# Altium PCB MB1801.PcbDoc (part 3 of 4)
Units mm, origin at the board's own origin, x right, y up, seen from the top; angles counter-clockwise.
Board outline 70.1 x 57.1 mm, 4 copper layers (Top Layer, Signal Layer 1, Signal Layer 2, Bottom Layer), stack 1.614 mm thick; 219 components, 166 nets, 1002 pads, 473 vias.
Unrouted connection lines stored in the file: 2.
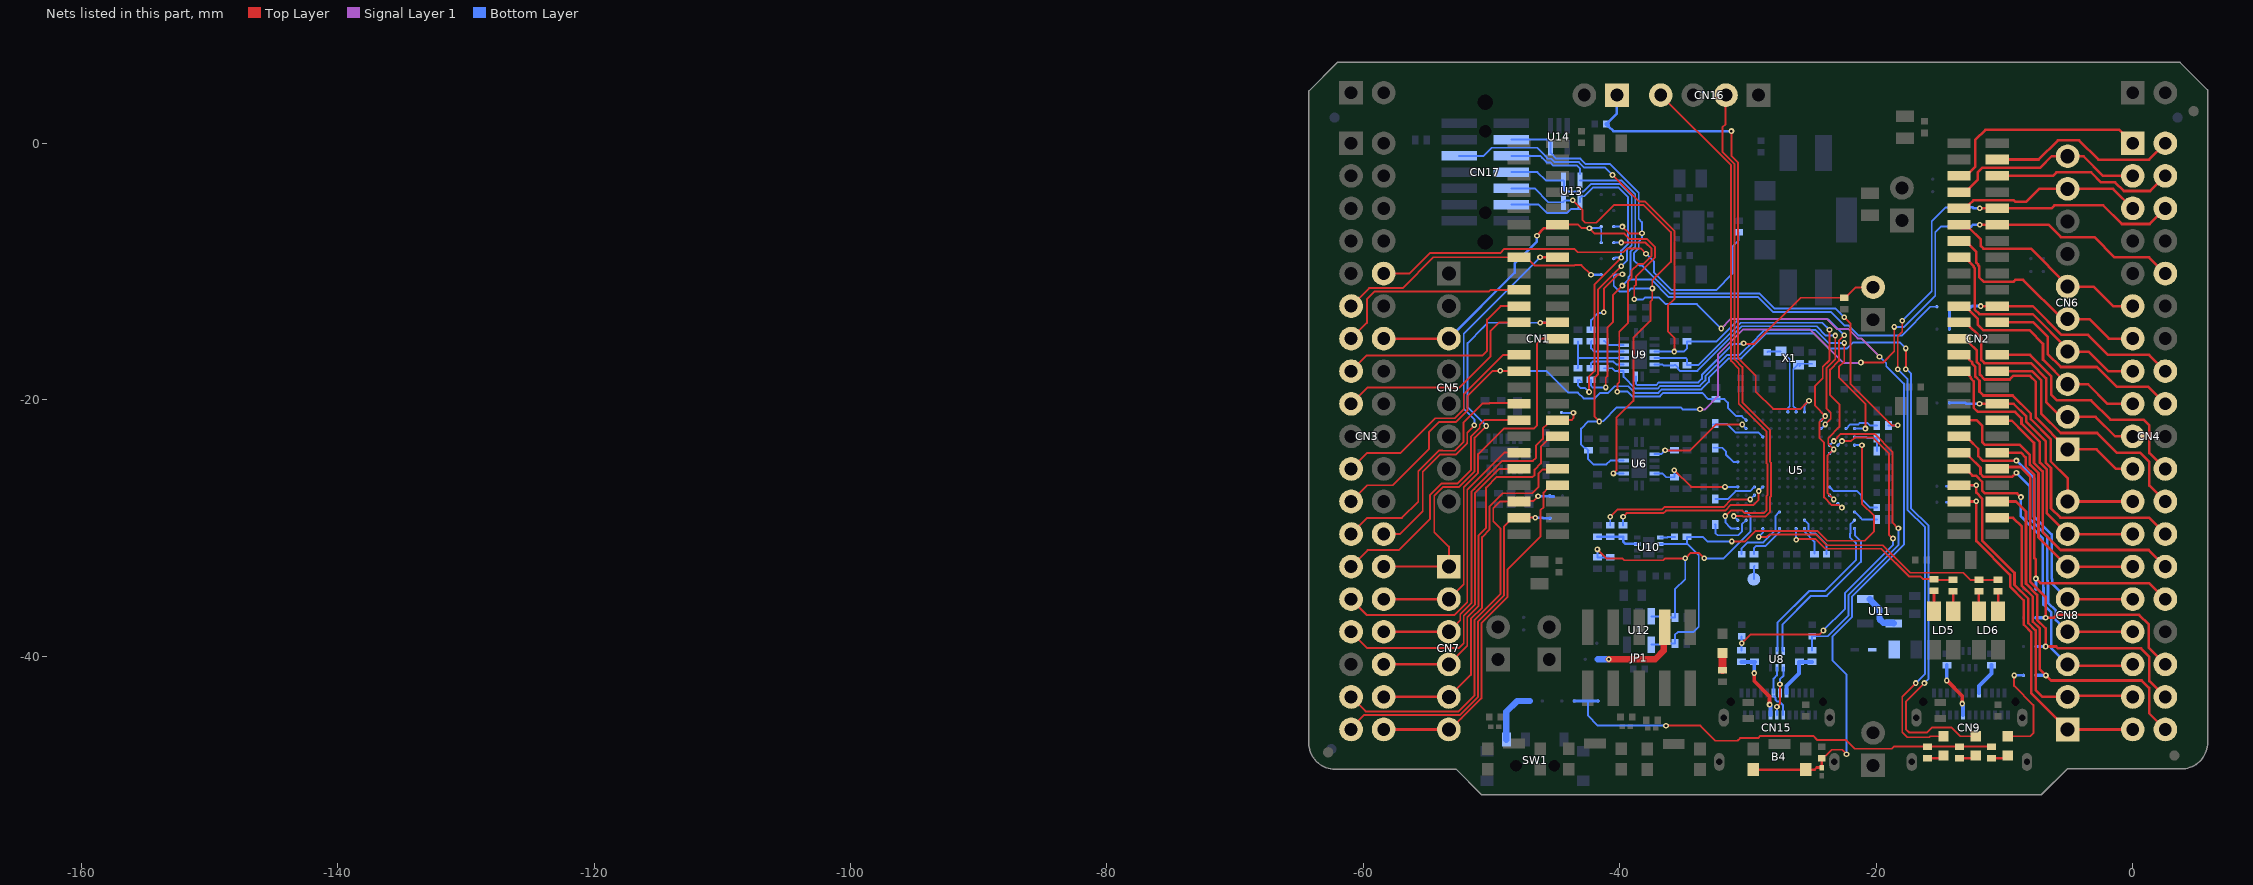
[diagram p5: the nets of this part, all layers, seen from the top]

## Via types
v1: diameter 0.45, hole 0.2, Top Layer to Bottom Layer, tented both sides, 473 vias

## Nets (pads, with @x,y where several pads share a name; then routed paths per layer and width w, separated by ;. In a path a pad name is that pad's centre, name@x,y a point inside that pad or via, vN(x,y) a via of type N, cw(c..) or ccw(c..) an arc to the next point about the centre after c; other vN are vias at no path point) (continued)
GPIO6/JTCK/SWCLK: CN1.15 CN3.11 SB15.1 | length 21.7
  Top Layer w0.15: CN3.11@-60.96,-12.7 -59.56,-11.3 -56.95,-11.3 -54.54,-8.89 CN1.15@-47.855,-8.89 -47.58,-9.165 -47.035,-9.165 -46.675,-9.525 -43.525,-9.525 -43.5,-9.5 -43,-9.5 v1(-42.25,-10.25)
  Bottom Layer w0.2: v1(-42.25,-10.25) SB15.1@-41.45,-10.25
GPIO7: CN1.16 CN3.26 | length 30.2
  Top Layer w0.15: CN3.26@-58.42,-30.48 -57.15,-30.48 -55.375,-28.705 -55.375,-25.614 -54.021,-24.26 -52.76,-24.26 -51.93,-23.43 -51.93,-23.387 -51.9,-23.357 -51.9,-22.575 -51.35,-22.025 v1(-51.35,-21.999)
  Top Layer w0.2: v1(-46.225,-8.9) -46.215,-8.89 CN1.16@-44.855,-8.89
  Bottom Layer w0.15: v1(-51.35,-21.999) -51.35,-21.525 -52.175,-20.7 -52.175,-14.85 v1(-46.225,-8.9)
GPIO8: CN1.19 CN3.13 | length 15.8
  Top Layer w0.15: CN3.13@-60.96,-15.24 -59.735,-14.015 -59.735,-12.16 -59.15,-11.575 -50.225,-11.575 -50.08,-11.43 ; -50.075,-11.425 -50.08,-11.43 ; CN1.19@-47.855,-11.43 -50.08,-11.43
GPIO9: CN1.21 CN3.15 | length 16.6
  Top Layer w0.15: CN3.15@-60.96,-17.78 -59.73,-16.55 -50.7,-16.55 -50.35,-16.2 -50.35,-15.598 -50.351,-15.597 -50.351,-13.751 -49.3,-12.7 CN1.21@-47.855,-12.7
GPIO10: CN1.23 CN3.17 | length 16.9
  Top Layer w0.15: CN3.17@-60.96,-20.32 -59.69,-19.05 -52.525,-19.05 -50.075,-16.6 -50.075,-15.485 -50.076,-15.484 -50.076,-14.626 -49.425,-13.975 ; -49.425,-13.97 CN1.23@-47.855,-13.97
GPIO11: CN1.24 CN3.28 CN7.1 SB27.1 | length 34.4
  Top Layer w0.15: CN3.28@-58.42,-33.02 CN7.1@-53.34,-33.02 -53.34,-31.46 -54.475,-30.325 -54.475,-27.484 -53.806,-26.815 -52.874,-26.815 -52.864,-26.825 -52.575,-26.825 -51.325,-25.575 -51.325,-22.964 -50.425,-22.064 v1(-50.425,-22.05)
  Top Layer w0.2: v1(-46.2,-14) -44.9,-14 CN1.24@-44.875,-13.975
  Bottom Layer w0.15: v1(-50.425,-22.05) -51.875,-20.6 -51.875,-15.586 -50.649,-14.36 -50.289,-14 v1(-46.2,-14)
  Bottom Layer w0.2: v1(-46.2,-14) SB27.1@-45.45,-14
GPIO12: CN1.26 CN3.30 CN7.2 | length 30.9
  Top Layer w0.15: CN7.2@-53.34,-35.56 -52.175,-34.395 -52.175,-26.825 -51.05,-25.7 -51.05,-24.25 -49.05,-22.25 -46.7,-22.25 -46.475,-22.025 -46.475,-15.65 -46.05,-15.225 CN1.26@-44.925,-15.225
  Top Layer w0.2: CN3.30@-58.42,-35.56 CN7.2@-53.34,-35.56
GPIO13: CN1.27 CN3.21 | length 17.5
  Top Layer w0.15: CN3.21@-60.96,-25.4 -59.71,-24.15 -57.1,-24.15 -54.4,-21.45 -53.033,-21.45 -53.028,-21.445 -52.874,-21.445 -52.175,-20.746 -52.175,-19.575 -49.125,-16.525 ; -49.125,-16.51 CN1.27@-47.855,-16.51
GPIO14: CN1.29 CN3.23 SB10.1 | length 19.8
  Top Layer w0.15: CN3.23@-60.96,-27.94 -59.695,-26.675 -57.725,-26.675 -54.9,-23.85 -54.9,-22.525 -54.1,-21.725 -52.765,-21.725 -51.875,-20.835 -51.875,-19.7 -49.925,-17.75 v1(-49.325,-17.75) CN1.29@-47.9,-17.75
  Bottom Layer w0.15: v1(-49.325,-17.75) -48.3,-17.75 SB10.1@-48.25,-17.7
GPIO15/OSC32_IN: CN1.33 CN3.25 | length 19.7
  Top Layer w0.15: CN3.25@-60.96,-30.48 -59.705,-29.225 -57,-29.225 -55.725,-27.95 -55.725,-25.575 -54.125,-23.975 -53.816,-23.975 -53.806,-23.985 -52.874,-23.985 -52.215,-23.326 -52.215,-23.305 -52.205,-23.295 -52.205,-21.78 -50.725,-20.3 -50.175,-20.3 ; -50.175,-20.275 CN1.33@-47.8,-20.275
GPIO16/OSC32_OUT: CN1.35 CN3.27 | length 20.6
  Top Layer w0.15: CN3.27@-60.96,-33.02 -59.665,-31.725 -57.225,-31.725 -54.8,-29.3 -54.8,-27.42 -53.92,-26.54 -52.679,-26.54 -51.6,-25.461 -51.6,-22.85 -50.925,-22.175 -50.925,-21.949 -50.566,-21.59 CN1.35@-47.855,-21.59
GPIO17: CN1.36 CN3.32 CN7.3 SB26.1 | length 29.3
  Top Layer w0.15: CN7.3@-53.34,-38.1 -52.45,-37.21 -52.45,-36.742 -51.575,-35.867 -51.575,-27.188 -51.35,-26.963 -51.35,-26.95 -49.175,-24.775 -46.775,-24.775 -46.55,-24.55 -46.55,-23.6 -46,-23.05 -46,-22.225 -45.68,-21.905 -45.68,-21.89 -45.38,-21.59 -43.765,-21.59 -43.625,-21.45 v1(-43.625,-21.025)
  Top Layer w0.2: CN3.32@-58.42,-38.1 CN7.3@-53.34,-38.1
  Bottom Layer w0.15: -44.425,-21.025 v1(-43.625,-21.025)
GPIO18: CN1.38 CN3.34 CN7.4 | length 28.3
  Top Layer w0.15: CN7.4@-53.34,-40.64 -51.9,-39.2 -51.9,-36.969 -51.025,-36.094 -51.025,-30.6 -50.425,-30 -50.425,-26.85 -49.6,-26.025 -46.8,-26.025 -46.65,-25.875 -46.65,-25.45 -46.165,-24.965 -46.165,-23.665 -45.68,-23.18 -45.68,-23.16 -45.38,-22.86 CN1.38@-44.855,-22.86
  Top Layer w0.2: CN3.34@-58.42,-40.64 CN7.4@-53.34,-40.64
GPIO19/OSC_IN: CN1.39 CN3.29 | length 24
  Top Layer w0.15: CN3.29@-60.96,-35.56 -59.72,-36.8 -52.9,-36.8 -51.9,-35.8 -51.9,-27.025 -49.005,-24.13 CN1.39@-47.855,-24.13
GPIO20/OSC_OUT: CN1.41 CN3.31 | length 25.8
  Top Layer w0.15: CN3.31@-60.96,-38.1 -59.685,-39.375 -52.55,-39.375 -52.175,-39 -52.175,-36.855 -51.3,-35.98 -51.3,-27.302 -49.398,-25.4 CN1.41@-47.855,-25.4
GPIO21: CN1.42 CN3.36 CN7.5 | length 28.5
  Top Layer w0.15: CN7.5@-53.34,-43.18 -51.625,-41.465 -51.625,-37.083 -50.75,-36.208 -50.75,-35.2 -50.75,-30.714 -50.15,-30.114 -50.15,-28.325 -49.125,-27.3 -48.6,-27.3 -46.85,-27.3 -46.337,-26.788 -46.337,-25.737 -46.05,-25.45 -45.425,-25.45 -45.225,-25.65 -45.105,-25.65 CN1.42@-44.855,-25.4
  Top Layer w0.2: CN3.36@-58.42,-43.18 CN7.5@-53.34,-43.18
GPIO22: CN1.44 CN3.38 CN7.6 | length 28
  Top Layer w0.15: CN7.6@-53.34,-45.72 -53.22,-45.72 -52.355,-44.855 -52.352,-44.855 -50.8,-43.303 -50.8,-37.425 -48.75,-35.375 -48.75,-33.225 -46.175,-30.65 -46.175,-28.601 -45.95,-28.376 -45.95,-27.735 -45.955,-27.73 -45.955,-27.482 -45.95,-27.478 -45.95,-27.25 -45.655,-26.955 -45.655,-26.945 -45.38,-26.67 CN1.44@-44.855,-26.67
  Top Layer w0.2: CN3.38@-58.42,-45.72 CN7.6@-53.34,-45.72
GPIO23: CN1.45 CN3.35 SB5.1 | length 31.4
  Top Layer w0.15: CN3.35@-60.96,-43.18 -59.835,-44.305 -52.58,-44.305 -51.35,-43.075 -51.35,-37.197 -49.3,-35.147 -49.3,-30.05 -49.875,-29.475 -49.875,-28.475 -49.34,-27.94 CN1.45@-47.855,-27.94 ; CN1.45@-47.855,-27.897 -46.722,-27.897 -46.38,-27.555 v1(-46.38,-27.525)
  Bottom Layer w0.2: v1(-46.38,-27.525) -45.513,-27.525 -45.499,-27.51 -45.465,-27.51 SB5.1@-45.45,-27.525 ; SB5.1@-45.45,-27.55 -45.166,-27.55
GPIO24: CN1.47 CN3.37 SB3.1 | length 29
  Top Layer w0.15: CN3.37@-61,-45.65 -59.93,-44.58 -52.466,-44.58 -51.075,-43.189 -51.075,-37.311 -49.025,-35.261 -49.025,-29.875 -48.68,-29.53 -48.68,-29.51 -48.38,-29.21 CN1.47@-47.855,-29.21 -47.845,-29.2 v1(-46.6,-29.2)
  Bottom Layer w0.2: v1(-46.6,-29.2) -46.016,-29.2 -45.966,-29.25 SB3.1@-45.45,-29.25
GPIO25: CN2.4 CN4.2 | length 14.5
  Top Layer w0.2: CN2.4@-10.195,-1.27 -7.341,-1.27 -5.842,0.229 -4.191,0.229 -2.687,-1.275 1.265,-1.275 CN4.2@2.54,0
GPIO26: CN2.5 CN4.1 | length 17.1
  Top Layer w0.2: CN2.5@-13.935,-2.54 -12.99,-2.54 -12.275,-1.825 -12.275,0.275 -11.5,1.05 -1.05,1.05 CN4.1@0,0
GPIO27: CN2.6 CN4.4 | length 13.9
  Top Layer w0.2: CN2.6@-10.195,-2.54 -6.223,-2.54 -5.958,-2.275 -3.237,-2.275 -2.462,-3.05 -1.375,-3.05 -0.7,-3.725 1.355,-3.725 CN4.4@2.54,-2.54
GPIO28: CN2.7 CN4.3 CN6.10 | length 16.1
  Top Layer w0.2: CN2.7@-13.935,-3.81 -13.04,-3.81 -12.765,-3.535 -12.765,-3.515 -12.1,-2.85 -12.1,-2.3 -11.7,-1.9 -7.209,-1.9 -6.325,-1.016 CN6.10@-5.08,-1.016 -3.835,-1.016 -2.311,-2.54 CN4.3@0,-2.54
GPIO29: CN2.9 CN4.5 CN6.9 | length 15.3
  Top Layer w0.2: CN2.9@-13.935,-5.08 -13.04,-5.08 -12.765,-4.805 -12.765,-4.79 -12.43,-4.455 -9.27,-4.455 -9.175,-4.55 -8.3,-4.55 -7.306,-3.556 CN6.9@-5.08,-3.556 -1.524,-3.556 CN4.5@0,-5.08
GPIO30: CN2.10 CN4.6 SB9.1 | length 16.8
  Top Layer w0.2: v1(-11.925,-5.075) -11.92,-5.08 CN2.10@-10.565,-5.08 -6.35,-5.08 -6.12,-4.85 -2.3,-4.85 -0.85,-6.3 1.32,-6.3 CN4.6@2.54,-5.08
  Bottom Layer w0.2: SB9.1@-13.05,-5 -12.5,-5 -12.425,-5.075 v1(-11.925,-5.075)
GPIO31: CN2.11 CN4.11 CN6.6 | length 16.5
  Top Layer w0.2: CN2.11@-13.565,-6.35 -13.29,-6.625 -12.75,-6.625 -11.85,-7.525 -11.85,-8.025 -11.65,-8.225 -7.95,-8.225 -5.2,-10.975 CN6.6@-5.2,-11.15 ; CN6.6@-5.08,-11.176 -3.049,-11.176 -1.525,-12.7 CN4.11@0,-12.7
GPIO32: CN2.12 CN4.10 SB12.1 | length 17.2
  Top Layer w0.2: v1(-11.925,-6.35) CN2.12@-10.565,-6.35 -6.579,-6.35 -5.604,-7.325 -3,-7.325 -1.425,-8.9 1.28,-8.9 CN4.10@2.54,-10.16
  Bottom Layer w0.2: SB12.1@-13.05,-6.5 -12.596,-6.5 -12.446,-6.35 v1(-11.925,-6.35)
GPIO33: CN2.13 CN4.13 CN6.5 | length 18.2
  Top Layer w0.2: CN2.13@-13.935,-7.62 -13.04,-7.62 -12.765,-7.895 -12.765,-7.91 -12.2,-8.475 -12.2,-9.305 -12.065,-9.44 -12.065,-9.514 -11.975,-9.603 -11.975,-10.45 -11.625,-10.8 -9.3,-10.8 -9.15,-10.65 -8.55,-10.65 -5.484,-13.716 CN6.5@-5.08,-13.716 -3.384,-13.716 -1.86,-15.24 CN4.13@0,-15.24
GPIO34: CN2.15 CN4.15 CN6.4 | length 19.3
  Top Layer w0.2: CN2.15@-13.565,-8.89 -13.04,-8.89 -12.765,-9.165 -12.765,-9.235 -12.415,-9.585 -12.415,-9.658 -12.335,-9.738 -12.335,-12.953 -11.963,-13.325 -7.8,-13.325 -5.08,-16.045 CN6.4@-5.08,-16.256 -3.444,-16.256 -1.92,-17.78 CN4.15@0,-17.78
GPIO37: CN2.21 CN4.17 CN6.3 | length 17.7
  Top Layer w0.2: CN2.21@-13.565,-12.7 -13.04,-12.7 -12.765,-12.975 -12.765,-13.013 -12.685,-13.092 -12.685,-13.098 -12.1,-13.683 -12.1,-14.15 -11.668,-14.582 -8.068,-14.582 -7,-15.65 -7,-16.875 -5.08,-18.795 -3.479,-18.796 -1.955,-20.32 CN4.17@0,-20.32
GPIO38: CN2.22 CN4.16 SB13.1 SB24.1 | length 20.7
  Top Layer w0.2: v1(-11.86,-12.7) -7.8,-12.7 -5.55,-14.95 -3.475,-14.95 -1.915,-16.51 1.27,-16.51 CN4.16@2.54,-17.78
  Bottom Layer w0.254: SB24.1@-14.3,-14.475 SB13.1@-14.3,-12.75 -12.575,-12.75 -12.525,-12.7 v1(-11.86,-12.7)
GPIO39: CN2.23 CN4.19 CN6.2 | length 19.7
  Top Layer w0.2: CN2.23@-13.935,-13.97 -13.04,-13.97 -11.81,-15.2 -11.81,-16.915 -11.575,-17.15 -7.95,-17.15 -6.75,-18.35 -6.75,-20.175 -5.589,-21.336 CN6.2@-5.08,-21.336 -2.889,-21.336 -1.365,-22.86 CN4.19@0,-22.86
GPIO40: CN2.24 CN4.18 | length 16.1
  Top Layer w0.2: CN2.24@-10.195,-13.97 -7.755,-13.97 -6.64,-15.085 -6.64,-16.423 -5.613,-17.45 -2.794,-17.45 -1.245,-18.999 1.219,-18.999 CN4.18@2.54,-20.32
GPIO41: CN2.25 CN4.21 CN6.1 | length 21
  Top Layer w0.2: CN2.25@-13.935,-15.24 -13.04,-15.24 -12.765,-15.515 -12.765,-15.56 -12.16,-16.165 -12.16,-17.061 -11.925,-17.296 -11.925,-18.048 -11.548,-18.425 -9.602,-18.425 -9.327,-18.15 -8,-18.15 -7.55,-18.6 -7.55,-21.406 CN6.1@-5.08,-23.876 -2.824,-23.876 -1.3,-25.4 CN4.21@0,-25.4
GPIO42: CN2.27 CN4.23 CN8.8 | length 21.7
  Top Layer w0.2: CN2.27@-13.565,-16.51 -13.04,-16.51 -12.765,-16.785 -12.765,-16.86 -12.51,-17.115 -12.51,-17.206 -12.275,-17.441 -12.275,-18.198 -11.95,-18.523 -11.95,-19.375 -11.65,-19.675 -9.375,-19.675 -7.955,-21.095 -7.955,-21.52 -6.4,-23.075 -6.4,-24.8 -5.08,-26.12 CN8.8@-5.08,-27.94 CN4.23@0,-27.94
GPIO43: CN2.28 CN4.22 | length 18.5
  Top Layer w0.2: CN2.28@-10.195,-16.51 -8.015,-16.51 -6.345,-18.18 -6.345,-19.63 -5.925,-20.05 -3.25,-20.05 -1.75,-21.55 0.825,-21.55 1.3,-22.025 1.3,-24.16 CN4.22@2.54,-25.4
GPIO44: CN2.29 CN4.25 CN8.7 | length 23.7
  Top Layer w0.2: CN2.29@-13.935,-17.78 -13.04,-17.78 -12.765,-18.055 -12.765,-18.11 -12.625,-18.25 -12.625,-18.343 -12.4,-18.568 -12.4,-20.632 -12.082,-20.95 -9.175,-20.95 -8.675,-21.45 -8.675,-21.875 -7.25,-23.3 -7.25,-24.912 -6.7,-25.462 -6.7,-28.86 CN8.7@-5.08,-30.48 CN4.25@0,-30.48
GPIO45: CN2.30 CN4.24 | length 19.5
  Top Layer w0.2: CN2.30@-10.195,-17.78 -7.845,-17.78 -7.15,-18.475 -7.15,-21.064 -5.614,-22.6 -2.775,-22.6 -1.225,-24.15 0.6,-24.15 1.3,-24.85 1.3,-26.7 CN4.24@2.54,-27.94
GPIO46: CN2.34 CN4.26 SB25.1 | length 24.2
  Top Layer w0.2: v1(-11.95,-20.325) -10.57,-20.325 CN2.34@-10.565,-20.32 -9.28,-20.32 -8.315,-21.285 -8.315,-21.71 -6.8,-23.225 -6.8,-24.902 -6.375,-25.327 -6.375,-28.475 -5.65,-29.2 1.26,-29.2 CN4.26@2.54,-30.48
  Bottom Layer w0.2: SB25.1@-14.3,-20.25 -13.05,-20.25 -12.975,-20.325 v1(-11.95,-20.325)
GPIO47: CN2.35 CN4.27 CN8.6 | length 22.8
  Top Layer w0.2: CN2.35@-13.935,-21.59 -12.185,-21.59 -11.75,-22.025 -11.75,-23.3 -11.715,-23.335 -11.715,-23.339 -11.553,-23.5 -8.85,-23.5 -8.025,-24.325 -8.025,-25.056 -7.35,-25.731 -7.35,-30.75 CN8.6@-5.08,-33.02 CN4.27@0,-33.02
GPIO48: CN2.36 CN4.28 | length 21.5
  Top Layer w0.2: CN2.36@-10.565,-21.59 -10.512,-21.643 -9.432,-21.643 -8.488,-22.586 -7.7,-23.375 -7.7,-24.921 -7.025,-25.596 -7.025,-30.325 -5.625,-31.725 1.245,-31.725 CN4.28@2.54,-33.02
GPIO49: CN2.37 CN4.29 CN8.5 | length 23.2
  Top Layer w0.2: CN2.37@-13.565,-22.86 -13.29,-23.135 -12.74,-23.135 -12.05,-23.825 -12.05,-24.4 -11.7,-24.75 v1(-9.075,-24.75) ; CN8.5@-5.08,-35.56 CN4.29@0,-35.56
  Bottom Layer w0.2: v1(-9.075,-24.75) -7.7,-26.125 -7.7,-29.125 -6.325,-30.5 -6.325,-33.957 -6.275,-34.007 -6.275,-34.365 CN8.5@-5.08,-35.56
GPIO50: CN2.39 CN4.31 CN8.4 | length 24.8
  Top Layer w0.2: CN2.39@-13.565,-24.13 -13.04,-24.13 -12.765,-24.405 -12.765,-24.41 -11.875,-25.3 -11.875,-25.775 -11.625,-26.025 -9.4,-26.025 v1(-9.075,-25.7) ; CN8.4@-5.08,-38.1 CN4.31@0,-38.1
  Bottom Layer w0.2: v1@-9.075,-25.725 -8.025,-26.775 -8.025,-29.325 -7.925,-29.425 ; -7.91,-29.41 -6.675,-30.645 -6.675,-34.101 -6.625,-34.151 -6.625,-34.51 -6.61,-34.525 -6.61,-35.84 -6,-36.45 -6,-37.18 CN8.4@-5.08,-38.1
GPIO51: CN2.40 CN4.30 SB4.1 | length 23.3
  Top Layer w0.2: CN2.40@-10.195,-24.13 -8.72,-24.13 -8.35,-24.5 -8.35,-25.19 -7.675,-25.865 -7.675,-32.35 -7.55,-32.475 v1(-7.55,-33.95) -7.2,-34.3 1.28,-34.3 CN4.30@2.54,-35.56
  Bottom Layer w0.254: SB4.1@-7.55,-34.75 v1(-7.55,-33.95)
GPIO52: CN2.41 CN4.33 CN8.3 | length 26
  Top Layer w0.2: CN2.41@-13.565,-25.4 -13.04,-25.4 -12.515,-25.925 -12.225,-25.925 -11.75,-26.4 -11.75,-27.075 -11.525,-27.3 -9.025,-27.3 v1(-8.725,-27.6) ; CN8.3@-5.08,-40.64 -4.953,-40.767 -0.127,-40.767 CN4.33@0,-40.64
  Bottom Layer w0.2: v1(-8.725,-27.6) -8.725,-29.1 -8.6,-29.225 ; -8.595,-29.22 -7.025,-30.79 -7.025,-34.246 -6.975,-34.296 -6.975,-34.655 -6.96,-34.67 -6.96,-35.99 -6.35,-36.6 -6.35,-39.4 CN8.3@-5.025,-40.725
GPIO53: CN2.42 CN4.34 SB6.1 | length 27.3
  Top Layer w0.2: CN2.42@-10.565,-25.4 -10.415,-25.25 -8.75,-25.25 -8,-26 -8,-34.175 -6.8,-35.375 v1(-6.8,-37) -6.125,-37 -5.9,-36.775 0.5,-36.775 1.25,-37.525 1.25,-39.35 CN4.34@2.54,-40.64
  Bottom Layer w0.254: SB6.1@-7.55,-37 v1(-6.8,-37)
GPIO54: CN2.43 CN4.35 CN8.2 SB8.1 | length 29.4
  Top Layer w0.2: CN2.43@-13.565,-26.67 v1@-12.205,-26.67 ; v1(-12.2,-26.675) -12.2,-27.25 -11.74,-27.71 -11.74,-30.99 -9.22,-33.51 -9.22,-34.44 -8.15,-35.51 -8.15,-37.425 -7.575,-38 -7.575,-42.625 -7.025,-43.175 -5.085,-43.175 CN8.2@-5.08,-43.18 ; CN8.2@-5.004,-43.104 -0.076,-43.104 CN4.35@0,-43.18
  Bottom Layer w0.2: -14.55,-26.75 SB8.1@-14.3,-26.75 -13.225,-26.75 -13.15,-26.675 v1(-12.2,-26.675)
GPIO55: CN2.45 CN4.37 CN8.1 SB7.1 | length 29.6
  Top Layer w0.2: CN2.45@-13.565,-27.94 -12.215,-27.94 v1(-12.2,-27.925) -12.2,-31.025 -9.57,-33.655 -9.57,-34.585 -8.5,-35.655 -8.5,-37.55 -7.9,-38.15 -7.9,-42.9 CN8.1@-5.08,-45.72 CN4.37@0,-45.72
  Bottom Layer w0.2: -14.525,-28 SB7.1@-14.3,-28 -13.525,-28 -13.45,-27.925 v1(-12.2,-27.925)
GPIO56: CN2.46 CN4.36 SB2.1 | length 26.5
  Top Layer w0.2: CN2.46@-10.565,-27.94 -9.11,-27.94 -8.325,-28.725 -8.325,-34.345 -7.45,-35.22 -7.45,-37.175 -6.8,-37.825 v1(-6.8,-39.25) ; v1@-6.775,-39.25 -5.975,-39.25 -5.825,-39.4 0.65,-39.4 1.3,-40.05 1.3,-41.94 CN4.36@2.54,-43.18
  Bottom Layer w0.254: SB2.1@-7.55,-39.25 v1(-6.8,-39.25)
GPIO57: CN2.48 CN4.38 SB11.1 | length 27.6
  Top Layer w0.2: CN2.48@-10.565,-29.21 -9.34,-29.21 -8.65,-29.9 -8.65,-34.515 -7.8,-35.365 -7.8,-37.3 -7.25,-37.85 -7.25,-41.025 v1(-6.775,-41.5) -6.375,-41.9 0.7,-41.9 1.275,-42.475 1.275,-44.455 CN4.38@2.54,-45.72
  Bottom Layer w0.254: SB11.1@-7.55,-41.5 v1(-6.775,-41.5)
HiZ_DBG_IF_EN: JP4.2 R47.2 U9.9 | length 22.5
  Top Layer w0.15: v1(-30.35,-15.605) -30.305,-15.65 -29.5,-15.65 -25.9,-12.05 -22.405,-12.05 -21.605,-11.25 JP4.2@-20.25,-11.25
  Bottom Layer w0.15: U9.9@-38.75,-18.2 -38.75,-18.775 -38.662,-18.863 -37.177,-18.863 -36.964,-18.65 -33.875,-18.65 -33.6,-18.375 -33.6,-18.1 -33.6,-18.075 -31.175,-15.65 -30.395,-15.65 v1(-30.35,-15.605)
JTCK/SWCLK: CN17.6 R34.2 SB15.2 U6.11 U13.5 | length 47.6
  Top Layer w0.15: v1(-43.675,-4.45) -42.9,-5.225 -42.9,-6 -42.7,-6.2 -41.85,-6.2 -40.475,-4.825 -38.139,-4.825 -36.025,-6.939 -36.025,-9.017 -36.025,-9.25 -37.475,-10.7 v1@-37.475,-11.3 ; v1(-41.25,-13.175) -41.25,-11.35 -40.131,-10.231 -39.806,-10.231 v1(-39.8,-10.225) ; v1(-40.5,-25.75) -40.5,-25.737 -40.275,-25.512 -40.275,-21.414 -38.95,-20.089 -38.95,-15.475 -38.95,-15.178 -37.625,-13.853 -37.625,-12.375 -37.475,-12.225 -37.475,-11.338 v1(-37.462,-11.325)
  Bottom Layer w0.15: CN17.6@-48.468,-3.52 -46.655,-3.52 -45.575,-4.6 U13.5@-44.4,-4.6 -44.4,-4.575 -44.275,-4.45 v1(-43.675,-4.45) ; R34.2@-42.25,-14.55 -42.25,-13.8 -41.682,-13.232 -41.307,-13.232 v1(-41.25,-13.175) ; v1(-40.5,-25.75) U6.11@-39.7,-25.75 ; v1(-39.8,-10.225) -40.422,-10.225 -40.447,-10.25 SB15.2@-40.475,-10.25 -40.475,-11.125 -40.025,-11.575 -39.35,-11.575 -39.1,-11.325 v1(-37.462,-11.325)
JTDI: CN17.10 R37.2 SB13.2 U13.3 | length 55.4
  Top Layer w0.15: v1(-41.1,-19.039) -41.1,-18.275 -40.975,-18.15 -40.975,-14.375 -40.525,-13.925 -40.525,-11.825 v1(-39.8,-11.1)
  Bottom Layer w0.15: CN17.10@-48.468,-0.98 -46.22,-0.98 -46.07,-1.13 -46.07,-1.145 -45.715,-1.5 -45.428,-1.5 -45.178,-1.75 -43.325,-1.75 -43.1,-1.975 U13.3@-43.1,-2.4 ; U13.3@-43.1,-2.9 -39.886,-2.9 -38.8,-3.986 -38.8,-8.075 -39.175,-8.45 -39.175,-10.275 -39.3,-10.4 -39.325,-10.425 -39.325,-10.625 ; R37.2@-42.25,-18.45 -42.25,-18.9 -42.1,-19.05 -41.11,-19.05 v1(-41.1,-19.039) ; v1(-39.8,-11.1) -39.325,-10.625 ; SB13.2@-15.275,-12.75 -15.775,-12.75 -18.025,-15 -21.375,-15 -22.175,-14.2 -22.486,-14.2 -22.718,-13.968 -23.511,-13.175 -28.039,-13.175 -29.214,-12 -36.186,-12 -37.561,-10.625 -39.325,-10.625
JTDO/SWO: CN17.8 R18.1 SB12.2 U6.13 U13.1 | length 79.5
  Top Layer w0.15: v1(-41.6,-21.7) -41.975,-21.325 -41.975,-18.275 -41.775,-18.075 -41.7,-18 -41.7,-11.4 v1(-39.9,-9.6) ; v1(-21.2,-17.1) -19.475,-17.1 -18.6,-16.225 v1(-18.6,-14.325)
  Signal Layer 1 w0.15: v1(-33.75,-20.75) -33.35,-20.75 -32.35,-19.75 -32.35,-16.503 -30.372,-14.525 -25.175,-14.525 -22.575,-17.125 -21.225,-17.125 v1(-21.2,-17.1)
  Bottom Layer w0.15: CN17.8@-48.468,-2.25 -46.425,-2.25 -45.775,-2.9 U13.1@-44.4,-2.9 -44.363,-2.937 -44.363,-3.637 -44.225,-3.775 -42.85,-3.775 -42.25,-3.175 -40,-3.175 -39.075,-4.1 -39.075,-7.95 -39.45,-8.325 -39.45,-9.15 v1(-39.9,-9.6) ; R18.1@-42.5,-23.95 -42.5,-24.625 -42.075,-25.05 -41.05,-25.05 -40.75,-24.75 U6.13@-39.7,-24.75 ; R18.1@-42.45,-23.95 -42.63,-23.77 -42.755,-23.77 -42.825,-23.7 -43.025,-23.5 -43.025,-22.25 -42.475,-21.7 v1(-41.6,-21.7) -41.582,-21.682 -41.307,-21.682 -40.225,-20.6 -35.25,-20.6 -35.1,-20.75 v1(-33.75,-20.75) ; v1(-18.6,-14.325) -17.825,-14.325 -15.4,-11.9 -15.4,-6.925 -14.975,-6.5 SB12.2@-14.025,-6.5
JTMS/SWDIO: CN17.4 R35.2 SB17.2 U13.4 | length 29.3
  Top Layer w0.15: v1(-42.4,-19.4) -42.4,-18.175 -41.975,-17.75 -41.975,-11 v1(-39.9,-8.925)
  Bottom Layer w0.15: CN17.4@-48.468,-4.79 -46.335,-4.79 -45.675,-5.45 -44.125,-5.45 -43.8,-5.125 U13.4@-43.125,-5.125 ; R35.2@-43.25,-18.45 -43.25,-18.9 -43.075,-19.075 -42.725,-19.075 v1(-42.4,-19.4) ; R35.2@-43.155,-18.45 R35.2@-42.975,-18.63 ; U13.4@-43.1,-4.6 -43.1,-4.262 -42.975,-4.137 -42.763,-4.137 -42.076,-3.45 -40.25,-3.45 -40.114,-3.45 -39.35,-4.214 -39.35,-7.825 -39.9,-8.375 v1(-39.9,-8.925) -40.372,-8.925 -40.447,-9 SB17.2@-40.475,-9
LD1: LD1.2 SB9.2 | length 48.1
  Top Layer w0.15: v1(-18.325,-17.625) -18.325,-15.05 -17.975,-14.7 v1(-17.975,-13.85) ; v1(-16.925,-42.1) -16.925,-42.125 -17.975,-43.175 -17.975,-45.95 -17.6,-46.325 -15.885,-46.325 -15.81,-46.25 LD1.2@-14.75,-46.25
  Bottom Layer w0.15: v1(-18.325,-17.625) -17.575,-18.375 -17.575,-28.575 -16.2,-29.95 -16.2,-41.375 v1(-16.925,-42.1) ; v1(-17.975,-13.85) -15.675,-11.55 -15.675,-6.1 -14.575,-5 SB9.2@-14.05,-5
LD2: LD2.2 SB10.2 | length 71.2
  Top Layer w0.15: v1(-17.701,-17.626) v1(-17.7,-16) ; v1(-16.25,-42.1) -17.7,-43.55 -17.7,-45.7 -17.45,-45.95 -16.025,-45.95 -15.625,-45.55 -14.15,-45.55 -13.45,-46.25 LD2.2@-12.25,-46.25
  Bottom Layer w0.15: SB10.2@-47.225,-17.75 -45.725,-17.75 -44.025,-19.45 -43.275,-19.45 -42.825,-19.9 -41.949,-19.9 -41.513,-19.465 -40.915,-19.465 -40.4,-18.95 -39.364,-18.95 -38.839,-19.475 -37,-19.475 -36.725,-19.2 -33.636,-19.2 -33.05,-18.614 -33.05,-18.303 -31.522,-16.775 -30.525,-16.775 -28.575,-14.825 -24.897,-14.825 -23.722,-16 -22.275,-16 -21.825,-15.55 -18.15,-15.55 v1(-17.7,-16) ; v1(-17.701,-17.626) -17.624,-17.626 -17.3,-17.95 -17.3,-19.275 -17.3,-28.45 -15.925,-29.825 -15.925,-41.775 v1(-16.25,-42.1)
LD3: LD3.2 SB11.2 | length 7.9
  Top Layer w0.15: LD3.2@-9.75,-46.25 -8,-46.25 -7.75,-46 -7.75,-43.825 -9.25,-42.325 v1(-9.25,-41.5)
  Bottom Layer w0.2: v1(-9.25,-41.5) SB11.2@-8.525,-41.5
NetC32_2: C32.2 JP3.1 U5.J1 | length 39.5
  Top Layer w0.15: v1(-31.3,0.95) -31.3,-0.982 -30.775,-1.507 -30.775,-16.75 -29.4,-18.125 -29.4,-19.375 -28.05,-20.725 -25.9,-20.725 v1(-25.25,-20.075)
  Bottom Layer w0.15: U5.J1@-25.6,-20.95 -25.6,-20.425 v1(-25.25,-20.075)
  Bottom Layer w0.2: C32.2@-40.92,1.37 -40.92,1.345 -40.895,1.32 -40.87,1.32 -40.5,0.95 v1(-31.3,0.95) ; C32.2@-40.92,1.63 -40.23,2.32 JP3.1@-40.23,3.75
  Bottom Layer w0.3: C32.2@-41.05,1.5 -41.05,1.475 -40.945,1.37 C32.2@-40.92,1.37
NetC33_2: C33.2 U5.J14 | length 3.5
  Bottom Layer w0.15: U5.J14@-25.6,-29.4 -25.425,-29.575 -25.275,-29.725 -25.275,-30.225 -25.075,-30.425 -24.775,-30.425 -23.875,-31.325 C33.2@-23.875,-32.05
NetC36_2: C36.2 U10.1 | length 1.2
  Bottom Layer w0.15: U10.1@-36.85,-30.75 -36.3,-30.75 -36.25,-30.7 C36.2@-35.75,-30.7 -35.725,-30.7 C36.2@-35.7,-30.725
NetC54_2: C54.2 D1.2 U11.3 U11.5 | length 3.1
  Bottom Layer w0.5: U11.5@-20.5,-35.55 -20.45,-35.6 -20.45,-35.65 -19.75,-36.35 -19.75,-37.107 -19.457,-37.4 -18.7,-37.4 U11.3@-18.65,-37.45
NetC56_2: C56.2 U5.M10 | length 4.5
  Bottom Layer w0.15: U5.M10@-23.65,-26.8 -23.325,-27.125 -21.5,-27.125 -21.175,-27.45 -21.175,-27.725 -20.5,-28.4 C56.2@-19.95,-28.4
NetC57_2: C57.2 U5.F13 | length 5.2
  Bottom Layer w0.15: C57.2@-30.5,-32.05 -30.5,-31.6 -30.025,-31.125 -28.8,-31.125 -27.875,-30.2 -27.875,-29.075 U5.F13@-27.55,-28.75
NetCN3_10: CN3.10 R1.1 | length 34
  Top Layer w0.15: CN3.10@-58.42,-10.16 -56.41,-10.16 -54.815,-8.565 -49.34,-8.565 -49.022,-8.247 -43.553,-8.247 -43.3,-8.5 -39.725,-8.5 -39.45,-8.225 -38.35,-8.225 v1@-37.975,-8.6 ; v1@-37.974,-8.599 v1(-37.96,-8.614)
  Bottom Layer w0.15: v1(-37.96,-8.614) -37.325,-9.249 -37.325,-10.083 -35.958,-11.45 -32.5,-11.45 -31.225,-10.175 -31.225,-8.075 -30.75,-7.6 R1.1@-30.75,-6.95
NetCN9_A5: CN9.A5 R11.2 | length 2.6
  Bottom Layer w0.3: CN9.A5@-11.99,-42.89 -11.99,-42.333 -11.004,-41.347 R11.2@-11.004,-40.697
NetCN9_B5: CN9.B5 R12.2 | length 4.4
  Top Layer w0.3: v1(-14.5,-41.9) -13.3,-43.1 v1(-13.3,-43.7)
  Bottom Layer w0.3: v1(-14.5,-41.9) R12.2@-14.5,-40.7 ; v1(-13.3,-43.7) -13.271,-43.729 -13.271,-43.844 -13.24,-43.876 CN9.B5@-13.24,-44.59
NetCN15_A5: CN15.A5 R14.1 R20.1 | length 3.9
  Bottom Layer w0.3: CN15.A5@-27.01,-42.89 -27.01,-42.333 -26.024,-41.347 -26.024,-40.447 -26.021,-40.45 R14.1@-26,-40.45 R20.1@-25,-40.45
NetCN15_B5: CN15.B5 R22.1 R23.1 | length 5.5
  Top Layer w0.3: v1(-29.52,-41.325) -29.52,-41.95 -28.32,-43.15 v1(-28.32,-43.775)
  Bottom Layer w0.3: R22.1@-30.5,-40.45 R23.1@-29.5,-40.45 R23.1@-29.45,-40.45 ; v1@-29.545,-41.325 -29.52,-41.3 R23.1@-29.52,-40.7 ; v1(-28.32,-43.775) -28.32,-43.816 -28.26,-43.876 CN15.B5@-28.26,-44.59
NetJP1_8: JP1.8 SB21.2 | length 7.3
  Top Layer w0.5: v1(-40.875,-40.25) -37.25,-40.25 -36.565,-39.565 -36.565,-37.815 JP1.8@-36.5,-37.75
  Bottom Layer w0.5: SB21.2@-41.725,-40.25 v1(-40.875,-40.25)
NetLD1_1: LD1.1 R6.2 | length 1.3
  Top Layer w0.2: R6.2@-16,-47.95 -14.925,-47.95 LD1.1@-14.75,-47.775
NetLD2_1: LD2.1 R7.2 | length 1.2
  Top Layer w0.2: R7.2@-13.5,-47.95 -12.325,-47.95 LD2.1@-12.275,-47.9
NetLD3_1: LD3.1 R8.2 | length 1.3
  Top Layer w0.2: R8.2@-11,-47.95 -9.975,-47.95 LD3.1@-9.775,-47.75
NetLD4_1: LD4.1 R13.1 | length 1.4
  Top Layer w0.6: R13.1@-32,-41.1 LD4.1@-32,-39.75
NetLD5_1: LD5.1 R48.1 | length 1.6
  Top Layer w0.2: LD5.1@-15.5,-36.5 R48.1@-15.5,-34.9
NetLD5_2: LD5.2 R50.1 | length 1.6
  Top Layer w0.2: LD5.2@-14,-36.5 R50.1@-14,-34.95
NetLD6_1: LD6.1 R49.1 | length 1.6
  Top Layer w0.2: LD6.1@-12,-36.5 R49.1@-12,-34.95
NetLD6_2: LD6.2 R51.2 | length 1.6
  Top Layer w0.2: LD6.2@-10.5,-36.5 R51.2@-10.5,-34.95
NetR6_1: R6.1 R7.1 R8.1 SB18.1 SB19.1 | length 35.9
  Top Layer w0.15: v1(-36.4,-45.425) -33.724,-45.425 -33.325,-45.824 -32.549,-46.6 -30.825,-46.6 -30.625,-46.4 -29.209,-46.4 -29.034,-46.225 -24.925,-46.225 -24.625,-46.525 -22.4,-46.525 -21.7,-47.225 -18.8,-47.225 -18.625,-47.05 R6.1@-16,-47.05 R7.1@-13.5,-47.05 R8.1@-11,-47.05
  Bottom Layer w0.15: -42.5,-43.5 -42.5,-44.625 -41.712,-45.412 -36.413,-45.412 v1(-36.4,-45.425)
  Bottom Layer w0.2: SB19.1@-43.55,-43.5 -42.5,-43.5 SB18.1@-41.7,-43.5
NetR21_2: R21.2 TP1.1 | length 1
  Bottom Layer w0.15: TP1.1@-29.55,-34 -29.55,-33.025 R21.2@-29.5,-32.975
NetR28_1: R28.1 R35.1 U9.12 | length 5.7
  Bottom Layer w0.15: R35.1@-43.3,-17.55 -43.25,-17.5 -43.25,-16.75 ; R28.1@-43.25,-15.45 -43.25,-16.75 ; U9.12@-39.7,-16.75 -43.25,-16.75
NetR29_1: R29.1 U5.P3 | length 2.6
  Bottom Layer w0.15: U5.P3@-22.35,-22.25 -22.02,-21.92 -21.394,-21.92 -21.299,-21.825 -20.674,-21.825 -20.499,-22 R29.1@-19.95,-22
NetR30_1: R30.1 U5.J15 | length 2.3
  Bottom Layer w0.15: U5.J15@-25.6,-30.05 -25.581,-30.069 -25.581,-30.308 -24.825,-31.064 R30.1@-24.825,-32
NetR32_1: R32.1 U9.14 | length 1.7
  Bottom Layer w0.15: R32.1@-41.225,-15.425 -41.18,-15.425 -40.975,-15.63 -40.975,-15.662 -40.887,-15.75 U9.14@-39.7,-15.75
NetR34_1: R34.1 U9.13 | length 3.2
  Bottom Layer w0.15: R34.1@-42.225,-15.425 R34.1@-42.25,-15.45 -42.25,-16 -42,-16.25 U9.13@-39.7,-16.25
NetR37_1: R37.1 U9.11 | length 3
  Bottom Layer w0.15: R37.1@-42.25,-17.475 -42.25,-17.15 -42.125,-17.025 -40.5,-17.025 -40.275,-17.25 U9.11@-39.7,-17.25
NetR39_1: R39.1 U5.D4 | length 4.3
  Bottom Layer w0.15: R39.1@-32.725,-21.925 R39.1@-32.55,-21.925 ; R39.1@-32.55,-21.875 -31.675,-21.875 -30.975,-22.575 -29.175,-22.575 U5.D4@-28.85,-22.9
NetR43_1: R43.1 R44.1 R45.1 U10.7 | length 3.5
  Bottom Layer w0.2: R45.1@-41.75,-30.7 R44.1@-40.75,-30.7 R43.1@-39.75,-30.7 -39.75,-31.075 -39.575,-31.25 U10.7@-38.65,-31.25
NetR57_1: R57.1 U5.R13 | length 2
  Bottom Layer w0.15: U5.R13@-21.7,-28.75 -21.225,-29.225 -21.1,-29.35 R57.1@-19.95,-29.35
NetR58_1: R58.1 U5.B14 | length 4
  Bottom Layer w0.15: R58.1@-32.575,-29.725 R58.1@-32.55,-29.75 -32.55,-30.4 -32.375,-30.575 -30.75,-30.575 -30.475,-30.3 -30.475,-29.725 U5.B14@-30.15,-29.4
NetSB22_2: SB22.2 SW1.3 | length 4.3
  Bottom Layer w0.5: SW1.3@-48.85,-46.509 -48.85,-44.35 -48,-43.5 SB22.2@-47.025,-43.5
NRST: CN17.12 R29.2 SB30.2 U14.5 | length 49.6
  Top Layer w0.15: v1(-39.801,-6.501) -39.275,-7.025 v1(-38.275,-7.025) ; v1(-22.5,-13.575) -22,-14.075 -22,-18.786 -18.786,-22 v1(-18.325,-22)
  Bottom Layer w0.15: CN17.12@-48.468,0.29 -45.65,0.29 -45.535,0.175 -45.525,0.175 -45.4,0.05 -45.4,-0.75 -44.95,-1.2 -43.075,-1.2 -42.65,-1.625 -40.75,-1.625 -38.525,-3.85 -38.525,-5.9 -38.275,-6.15 v1(-38.275,-7.025) -38.275,-7.425 -38.525,-7.675 -38.525,-8.189 -38.9,-8.564 -38.9,-8.749 -38.9,-9.101 -38.9,-9.111 -38.461,-9.55 -38.247,-9.55 -36.072,-11.725 -29.1,-11.725 -27.925,-12.9 -23.175,-12.9 v1(-22.5,-13.575) ; SB30.2@-40.475,-6.5 v1(-39.801,-6.501) ; R29.2@-19.05,-22 v1(-18.325,-22)
RSTN: B4.2 B4.4 C62.1 CN1.12 CN3.14 CN5.3 SB29.1 SB30.1 U19.1 | length 97.8
  Top Layer w0.15: CN1.12@-44.855,-6.35 -43.262,-6.35 -42.987,-6.625 v1(-42.375,-6.625) -41.95,-7.05 -39.639,-7.05 -39.214,-7.475 -37.875,-7.475 -37.25,-8.1 -37.25,-8.898 -38.725,-10.373 -38.725,-10.861 -38.725,-11.019 -38.878,-11.172 -38.878,-12.172 v1(-38.875,-12.175) ; C62.1@-24.25,-47.95 -24.07,-47.77 -23.939,-47.77 -23.469,-47.3 -22.65,-47.3 -22.325,-47.625 v1(-22.325,-47.65)
  Top Layer w0.2: CN3.14@-58.42,-15.24 CN5.3@-53.34,-15.24 ; v1(-46.463,-7.212) -46.463,-7.183 -45.905,-6.625 -45.13,-6.625 CN1.12@-44.855,-6.35 ; B4.4@-29.6,-48.85 B4.2@-25.5,-48.85 -24.8,-48.85 -24.638,-48.688 U19.1@-24.25,-48.688 C62.1@-24.25,-47.95
  Signal Layer 1 w0.15: v1(-32.1,-14.45) -31.35,-13.7 -23.85,-13.7 -23.075,-14.475 -22.2,-14.475 -21.45,-15.225 -21.175,-15.225 v1(-19.75,-16.65)
  Bottom Layer w0.15: v1(-42.375,-6.625) -41.538,-6.625 -41.45,-6.713 SB29.1@-41.45,-7.75 ; v1(-38.875,-12.175) -38.175,-12.175 -38.025,-12.025 -36.95,-12.025 -36.425,-12.55 -34,-12.55 v1(-32.1,-14.45) ; v1(-22.325,-47.65) -22.325,-41.425 -23.4,-40.35 -23.4,-38.45 -21.9,-36.95 -21.9,-35.35 -17.85,-31.3 -17.85,-18.75 -19.225,-17.375 -19.225,-17.175 v1(-19.75,-16.65)
  Bottom Layer w0.2: CN5.3@-53.34,-15.24 -48.196,-10.096 -48.196,-9.371 -46.475,-7.65 -46.475,-7.224 v1(-46.463,-7.212)
STLK_LED: R49.2 R51.1 U5.D15 | length 21
  Top Layer w0.15: v1(-29.175,-30.7) -28.525,-30.7 -28.325,-30.5 -24.725,-30.5 -23.875,-31.35 -19.486,-31.35 -17.336,-33.5 -13.225,-33.5 -12.675,-34.05 R49.2@-12,-34.05 R51.1@-10.5,-34.05
  Bottom Layer w0.15: v1(-29.175,-30.7) -28.85,-30.375 U5.D15@-28.85,-30.05
STLK_OSC_IN: C28.2 U5.G1 X1.1 | length 5.7
  Bottom Layer w0.15: C28.2@-28.5,-16.3 -28.45,-16.25 X1.1@-27.45,-16.25 ; X1.1@-27.05,-16.55 -26.75,-16.85 -26.75,-20.525 -26.9,-20.675 U5.G1@-26.9,-20.95
STLK_OSC_OUT: C29.1 U5.H1 X1.3 | length 5.2
  Bottom Layer w0.15: U5.H1@-26.25,-20.95 -26.25,-20.725 -26.475,-20.5 -26.475,-17.625 -26.15,-17.3 -26.15,-17.2 C29.1@-25,-17.2 ; X1.3@-25.988,-17.363 X1.3@-25.95,-17.325
STLK_SWCLK: CN16.2 U5.A14 | length 37.6
  Top Layer w0.15: CN16.2@-31.75,3.625 -31.75,1.5 -32,1.25 -32,-0.671 -31.05,-1.621 -31.05,-16.864 -30.45,-17.464 -30.45,-20.2 -28.3,-22.35 -28.3,-24.825 -28.2,-24.925 -28.2,-27.529 -28.275,-27.604 -28.275,-28.725 -28.675,-29.125 -30.375,-29.125 -30.425,-29.075 v1(-31.125,-29.075)
  Bottom Layer w0.15: v1(-31.125,-29.075) U5.A14@-30.8,-29.4
STLK_SWDIO: CN16.4 U5.A15 | length 41.1
  Top Layer w0.15: CN16.4@-36.81,3.75 -31.325,-1.735 -31.325,-15.725 -31.325,-16.351 -31.325,-16.978 -30.725,-17.578 -30.725,-20.314 -28.575,-22.464 -28.575,-24.939 -28.475,-25.039 -28.475,-27.415 -28.55,-27.49 -28.55,-28.611 -28.789,-28.85 -30.25,-28.85 -30.45,-28.65 -31.35,-28.65 v1(-31.775,-29.075)
  Bottom Layer w0.15: v1(-31.775,-29.075) -31.775,-29.575 -31.375,-29.975 -31.3,-30.05 U5.A15@-30.8,-30.05
STLK_UCPD_CC1_C: C26.1 R20.2 U5.M5 | length 25
  Top Layer w0.15: v1(-23.325,-23.225) -22.775,-22.675 -21.026,-22.675 -20.136,-22.675 -18.75,-24.061 -18.75,-29.575 v1@-18.275,-30.05
  Bottom Layer w0.15: R20.2@-25,-39.55 C26.1@-25,-38.45 -23.8,-38.45 -22.4,-37.05 ; U5.M5@-23.65,-23.55 v1(-23.325,-23.225) ; -22.394,-37.056 -22.175,-36.836 -22.175,-35.236 -18.275,-31.336 v1(-18.275,-30.025)
STLK_UCPD_CC2_C: C27.1 R22.2 U5.N5 | length 28.8
  Top Layer w0.15: v1(-30.5,-39) -29.8,-38.3 -24.425,-38.3 v1(-24.125,-38) ; v1(-22.675,-23.225) -21.975,-23.225 -21.7,-22.95 -20.25,-22.95 -19.025,-24.175 -19.025,-30.55 v1@-18.775,-30.8
  Bottom Layer w0.15: R22.2@-30.5,-39.55 v1(-30.5,-39) C27.1@-30.5,-38.45 ; v1(-24.125,-38) -22.45,-36.325 -22.45,-35.1 -18.7,-31.35 v1(-18.7,-30.825) ; U5.N5@-23,-23.55 v1(-22.675,-23.225)
STLK_USB_CN_N: CN15.A7 CN15.B7 U8.2 | length 4
  Bottom Layer w0.155: CN15.A7@-28.02,-43.08 -27.975,-43.125 -27.937,-43.162 -27.862,-43.238 -27.862,-43.419 -27.759,-43.522 -27.573,-43.522 -27.275,-43.82 -27.275,-44.025 ; CN15.A7@-28.01,-42.89 -28.01,-41.76 -27.75,-41.5 U8.2@-27.75,-40.9 ; -27.272,-44.025 -27.272,-44.578 CN15.B7@-27.26,-44.59
STLK_USB_CN_P: CN15.A6 CN15.B6 U8.1 | length 4.5
  Top Layer w0.155: v1(-27.75,-43.95) -27.75,-43.942 -27.52,-43.712 v1(-27.52,-42.2)
  Bottom Layer w0.155: CN15.B6@-27.76,-44.59 -27.755,-44.585 -27.755,-43.955 v1(-27.75,-43.95) ; CN15.A6@-27.545,-42.8 -27.515,-42.77 -27.515,-42.205 v1(-27.52,-42.2) -27.52,-41.82 -27.25,-41.55 U8.1@-27.25,-40.9
STLK_USB_N: U5.R14 U8.5 | length 13.7
  Bottom Layer w0.15: -22.028,-29.727 -21.803,-29.503
  Bottom Layer w0.155: U8.5@-27.75,-39.6 -27.702,-39.552 -27.702,-39.299 -27.691,-39.287 -27.691,-37.366 -25.25,-34.925 -24.014,-34.925 -21.581,-32.492 -21.581,-31.212 -22.036,-30.758 -22.036,-30.429 -22.028,-30.421 -22.028,-29.727
STLK_USB_P: U5.R15 U8.6 | length 13
  Bottom Layer w0.15: U5.R15@-21.7,-30.05 U5.R15@-21.657,-30.094
  Bottom Layer w0.155: U8.6@-27.25,-39.6 -27.298,-39.552 -27.298,-39.299 -27.31,-39.287 -27.31,-37.523 -25.092,-35.306 -24.106,-35.306 ; -24.1,-35.3 -24.094,-35.306 -23.856,-35.306 -21.2,-32.65 -21.2,-31.055 -21.655,-30.6 -21.655,-30.271 -21.657,-30.269 U5.R15@-21.657,-30.094
STLK_VCP_RX: R55.1 U5.C10 | length 3.4
  Bottom Layer w0.15: R55.1@-32.55,-27.75 -31.6,-27.75 -30.975,-27.125 -29.825,-27.125 U5.C10@-29.5,-26.8
STLK_VCP_TX: R56.1 U5.A7 | length 2.5
  Bottom Layer w0.15: R56.1@-32.704,-23.75 -32,-23.75 -31.725,-24.025 -31.725,-24.275 -31.15,-24.85 U5.A7@-30.8,-24.85
SW_DIR: R41.2 U5.R3 U9.10 | length 30.7
  Top Layer w0.15: v1(-22.499,-15.575) v1(-22.499,-15.575) -22.5,-17.024 -22.925,-17.449 -22.925,-18.25 -20.85,-20.325 v1(-20.85,-22.25)
  Bottom Layer w0.15: R41.2@-41.25,-17.55 -40.6,-17.55 -40.4,-17.75 U9.10@-39.7,-17.75 -39.7,-18.225 -38.787,-19.138 -37.052,-19.138 -36.839,-18.925 -33.75,-18.925 -33.325,-18.5 -33.325,-18.275 ; -33.325,-18.189 -31.636,-16.5 -30.65,-16.5 -30.18,-16.03 -30.174,-16.03 -29.925,-15.781 -29.925,-15.775 -28.7,-14.55 -28.275,-14.55 -24.775,-14.55 -23.75,-15.575 v1(-22.499,-15.575) ; U5.R3@-21.7,-22.25 v1(-20.85,-22.25)
T_DBG_BOOT: R59.2 U5.B3 U6.3 | length 9
  Top Layer w0.15: v1(-36.475,-23.95) -34.525,-23.95 -32.513,-21.938 v1(-30.462,-21.938)
  Bottom Layer w0.15: U6.3@-37.3,-24.25 -37.288,-24.238 -36.763,-24.238 v1(-36.475,-23.95) R59.2@-35.75,-23.95 ; v1(-30.462,-21.938) U5.B3@-30.15,-22.25
T_DBG_RST: R2.2 SB29.2 U5.B2 | length 27.1
  Top Layer w0.15: v1(-40.2,-19.375) -40.2,-18.8 -40.05,-18.65 -40.05,-14.711 -39.35,-14.011 -39.35,-11.125 -39.35,-11.014 -39.35,-10.786 -39.344,-10.781 ; v1(-39.9,-7.75) -38,-7.75 -37.525,-8.225 -37.525,-8.784 -38.166,-9.425 -38.583,-9.425 -39.1,-9.942 -39.1,-10.525 -39.35,-10.775
  Bottom Layer w0.15: SB29.2@-40.475,-7.75 v1(-39.9,-7.75) ; v1(-40.2,-19.375) -39.4,-19.375 -39.025,-19.75 -36.875,-19.75 -36.6,-19.475 -33.574,-19.475 -33.099,-19.95 R2.2@-32.5,-19.95 -31.85,-19.95 -31.575,-20.225 -31.575,-20.628 -30.928,-21.275 -30.475,-21.275 U5.B2@-30.15,-21.6
T_JRCLK: R17.1 U5.A10 U6.6 | length 7.7
  Top Layer w0.15: v1(-35.75,-25.5) -34.45,-26.8 v1(-31.8,-26.8)
  Bottom Layer w0.15: U6.6@-37.3,-25.75 -36.675,-25.75 -36.375,-26.05 R17.1@-35.775,-26.05 ; R17.1@-35.75,-26.05 v1(-35.75,-25.5) ; v1(-31.8,-26.8) -31.775,-26.8 U5.A10@-30.8,-26.8
T_JTDI: R27.1 U5.L3 U9.6 | length 24.1
  Top Layer w0.15: v1(-23.975,-21.925) -23.55,-21.5 -23.55,-21.025 -23.9,-20.675 -23.9,-17.564 -23.2,-16.864 v1(-23.2,-15)
  Bottom Layer w0.15: U9.6@-37.3,-17.25 -36.675,-17.25 -36.6,-17.325 R27.1@-35.8,-17.325 ; R27.1@-35.75,-17.3 -35.655,-17.3 -35.475,-17.48 -35.475,-17.6 -35.325,-17.75 -34.825,-17.75 -33.95,-17.75 -30.475,-14.275 -24.65,-14.275 -23.925,-15 v1(-23.2,-15) ; U5.L3@-24.3,-22.25 v1(-23.975,-21.925)
T_MCO: R21.1 U5.F15 | length 3.3
  Bottom Layer w0.15: R21.1@-29.55,-32.05 -29.55,-31.575 -29.375,-31.4 -28.625,-31.4 -27.55,-30.325 U5.F15@-27.55,-30.05
T_PWR_EN: R46.2 R53.2 U5.R5 U10.2 U12.4 | length 37.5
  Top Layer w0.15: v1(-31.275,-31.05) -30.225,-31.05 -29.4,-30.225 -24.6,-30.225 -23.825,-31 -20.9,-31 -20.175,-30.275 -20.175,-29.05 -21.125,-28.1 v1(-21.125,-23.55)
  Bottom Layer w0.15: U12.4@-37.55,-39.1 -36.775,-39.1 -36.675,-39 R53.2@-35.7,-39 -35.7,-38.35 -35.475,-38.125 -34.275,-38.125 -33.85,-37.7 -33.85,-32.15 -34.75,-31.25 ; U10.2@-36.85,-31.25 -34.75,-31.25 ; v1(-31.275,-31.05) -33.175,-31.05 -33.525,-30.7 R46.2@-34.75,-30.7 -34.75,-31.25 ; U5.R5@-21.7,-23.55 v1(-21.125,-23.55)
T_PWR_EXT: R36.1 R38.1 U5.R4 | length 2.8
  Bottom Layer w0.15: U5.R4@-21.7,-22.9 -20.775,-22.9 -20.725,-22.95 -20.675,-23 R36.1@-19.975,-23 ; R38.1@-19.95,-24 R36.1@-19.95,-23
T_PWR_INT: R40.2 R42.2 R52.2 U5.B13 U12.3 | length 23.6
  Top Layer w0.15: v1(-41.75,-31.675) -41.05,-32.375 -39.825,-32.375 -39.675,-32.525 -36.6,-32.525 -36.45,-32.375 -34.88,-32.375 -34.455,-31.95 -33.85,-31.95 v1(-33.425,-32.375)
  Bottom Layer w0.15: v1(-41.75,-31.675) R42.2@-41.75,-32.3 R40.2@-40.825,-32.3 ; U12.3@-37.55,-36.9 -36.725,-36.9 -36.675,-36.95 -36.625,-37 R52.2@-35.725,-37 ; R52.2@-35.7,-37 -35.7,-34.8 -34.9,-34 v1(-34.9,-32.375) ; v1(-33.425,-32.375) -31.9,-32.375 -29.825,-30.3 -29.825,-29.075 U5.B13@-30.15,-28.75
T_PWR_LED: R48.2 R50.2 U5.H15 | length 14.5
  Top Layer w0.15: v1(-26.25,-30.925) -26.2,-30.875 -24.739,-30.875 -23.989,-31.625 -19.6,-31.625 -17.45,-33.775 -16.575,-33.775 -16.35,-34 R48.2@-15.5,-34 -15.45,-34.05 R50.2@-14,-34.05
  Bottom Layer w0.15: v1(-26.25,-30.925) U5.H15@-26.25,-30.05
T_PWR_SEL1: R43.2 U5.D10 | length 12.9
  Top Layer w0.15: v1(-39.75,-29.125) -39.475,-28.85 -36.6,-28.85 -36.4,-28.65 -31.786,-28.65 -31.336,-28.2 -29.575,-28.2 -29.175,-27.8 v1(-29.175,-27.125)
  Bottom Layer w0.15: R43.2@-39.75,-29.8 v1(-39.75,-29.125) ; v1(-29.175,-27.125) U5.D10@-28.85,-26.8
T_PWR_SEL2: R44.2 U5.C11 | length 12.6
  Top Layer w0.15: v1(-40.75,-29.125) -40.2,-28.575 -36.725,-28.575 -36.525,-28.375 -31.9,-28.375 -31.3,-27.775 v1(-29.825,-27.775)
  Bottom Layer w0.15: R44.2@-40.75,-29.8 v1(-40.75,-29.125) ; v1(-29.825,-27.775) U5.C11@-29.5,-27.45
T_SWCLK: CN17.9 R25.1 U5.M6 U5.M11 U9.4 | length 61.7
  Top Layer w0.15: v1(-40.575,-2.475) -38.5,-4.55 -38.025,-4.55 -35.75,-6.825 -35.75,-12.15 -36.25,-12.65 -36.25,-14.675 -35.75,-15.175 v1(-35.75,-16.25) ; v1(-23.325,-27.775) -23.8,-27.3 -23.8,-24.35 v1(-23.325,-23.875) -23.75,-23.45 -23.75,-23 -23.725,-22.975 -22.875,-22.125 -22.875,-20.375 -23.6,-19.65 -23.6,-17.653 -22.925,-16.978 -22.925,-15.4 v1(-22.5,-14.975)
  Bottom Layer w0.15: CN17.9@-52.532,-0.98 -50.63,-0.98 -50,-0.35 -46.461,-0.35 -45.795,-1.016 -45.795,-1.031 -45.619,-1.207 -45.332,-1.207 -45.064,-1.475 -43.189,-1.475 -42.764,-1.9 -41.15,-1.9 v1(-40.575,-2.475) ; U9.4@-37.3,-16.25 v1(-35.75,-16.25) -35,-16.25 -34.75,-16 R25.1@-34.75,-15.45 -32.45,-15.45 -30.725,-13.725 -23.75,-13.725 v1(-22.5,-14.975) ; U5.M11@-23.65,-27.45 v1(-23.325,-27.775) ; U5.M6@-23.65,-24.2 v1(-23.325,-23.875)
T_SWDIO: R26.1 U5.L2 U5.N12 U9.5 | length 32.6
  Top Layer w0.15: -24.1,-23.325 -24.425,-23 -24.425,-21.725 v1(-23.975,-21.275) -24.775,-20.475 -24.775,-18.925 -24.175,-18.325 -24.175,-17.45 -23.65,-16.925 v1(-23.65,-14.55) ; -24.075,-23.325 -24.075,-27.626 -23.501,-28.2 -22.921,-28.2 -22.705,-28.416 v1(-22.683,-28.416)
  Bottom Layer w0.15: U9.5@-37.3,-16.75 -34.85,-16.75 -34.75,-16.85 R26.1@-34.75,-17.3 -33.889,-17.3 -30.589,-14 -24.2,-14 v1(-23.65,-14.55) ; U5.L2@-24.3,-21.6 v1(-23.975,-21.275) ; U5.N12@-23,-28.1 v1(-22.683,-28.416)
